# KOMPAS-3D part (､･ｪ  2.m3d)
File: created 29.01.2016 13:47:21, last saved 25.07.2016 11:42:03.
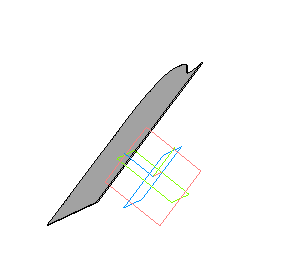
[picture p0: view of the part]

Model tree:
1. Эскиз:1
2. Операция выдавливания:1
     Толщина стенки 2 = 18; Расстояние 1 = 0.8
3. Эскиз:5
4. Вырезать элемент выдавливания:2
     Расстояние 1 = 10
5. Эскиз:6
6. Вырезать элемент выдавливания:3
     Расстояние 1 = 400
7. Эскиз:7
8. Вырезать элемент выдавливания:4
     Расстояние 2 = 400; Расстояние 1 = 400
